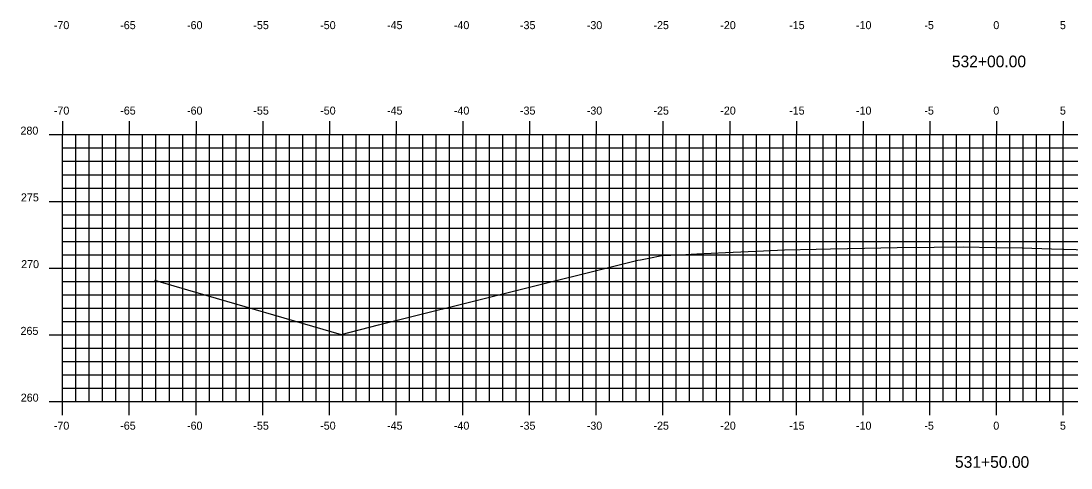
# Model space of a CAD drawing. Extents: x 1170543 to 1177585, y 609599 to 610623.
# Drawn here: x 1176762.5 to 1176841.2, y 610272.8 to 610306.3 of the extents above; entities that cross this region are included whole.
import ezdxf

# ---------------------------------------------------------------- set-up
doc = ezdxf.new("R2010")
doc.units = 0
for name, color, linetype in [('H_V ANNOTATION', 7, 'Continuous'), ('MAJOR', 7, 'Continuous'), ('MINOR', 7, 'Continuous'), ('S_Roadway_Centerline', 7, 'Continuous')]:
    doc.layers.add(name, color=color, linetype=linetype)

msp = doc.modelspace()

# ---------------------------------------------------------------- linework, layer by layer
at = {"layer": 'MAJOR'}
for p, q in [((1176765.654, 610298.803), (1176765.654, 610297.801)), ((1176770.654, 610298.803), (1176770.654, 610297.801)), ((1176775.654, 610298.803), (1176775.654, 610297.801)), ((1176780.654, 610298.803), (1176780.654, 610297.801)), ((1176785.654, 610298.803), (1176785.654, 610297.801)), ((1176790.654, 610298.803), (1176790.654, 610297.801)), ((1176795.654, 610298.803), (1176795.654, 610297.801)), ((1176800.654, 610298.803), (1176800.654, 610297.801)), ((1176805.654, 610298.803), (1176805.654, 610297.801)), ((1176810.654, 610298.803), (1176810.654, 610297.801)), ((1176815.654, 610298.803), (1176815.654, 610297.801)), ((1176820.654, 610298.803), (1176820.654, 610297.801)), ((1176825.654, 610298.803), (1176825.654, 610297.801)), ((1176830.654, 610298.803), (1176830.654, 610297.801)), ((1176835.654, 610298.803), (1176835.654, 610297.801)), ((1176840.654, 610298.803), (1176840.654, 610297.801)), ((1176764.652, 610297.801), (1176765.654, 610297.801)), ((1176765.654, 610297.801), (1176905.654, 610297.801)), ((1176765.654, 610277.801), (1176765.654, 610297.801)), ((1176765.654, 610277.801), (1176765.654, 610297.801)), ((1176765.654, 610297.801), (1176905.654, 610297.801)), ((1176770.654, 610277.801), (1176770.654, 610297.801)), ((1176775.654, 610277.801), (1176775.654, 610297.801)), ((1176780.654, 610277.801), (1176780.654, 610297.801)), ((1176785.654, 610277.801), (1176785.654, 610297.801)), ((1176790.654, 610277.801), (1176790.654, 610297.801)), ((1176795.654, 610277.801), (1176795.654, 610297.801)), ((1176800.654, 610277.801), (1176800.654, 610297.801)), ((1176805.654, 610277.801), (1176805.654, 610297.801)), ((1176810.654, 610277.801), (1176810.654, 610297.801)), ((1176815.654, 610277.801), (1176815.654, 610297.801)), ((1176820.654, 610277.801), (1176820.654, 610297.801)), ((1176825.654, 610277.801), (1176825.654, 610297.801)), ((1176830.654, 610277.801), (1176830.654, 610297.801)), ((1176835.654, 610277.801), (1176835.654, 610297.801)), ((1176840.654, 610277.801), (1176840.654, 610297.801)), ((1176764.652, 610292.801), (1176765.654, 610292.801)), ((1176765.654, 610292.801), (1176905.654, 610292.801)), ((1176764.652, 610287.801), (1176765.654, 610287.801)), ((1176765.654, 610287.801), (1176905.654, 610287.801)), ((1176764.652, 610282.801), (1176765.654, 610282.801)), ((1176765.654, 610282.801), (1176905.654, 610282.801)), ((1176764.652, 610277.801), (1176765.654, 610277.801)), ((1176765.654, 610277.801), (1176905.654, 610277.801)), ((1176765.654, 610277.801), (1176905.654, 610277.801)), ((1176765.654, 610276.799), (1176765.654, 610277.801)), ((1176770.654, 610276.799), (1176770.654, 610277.801)), ((1176775.654, 610276.799), (1176775.654, 610277.801)), ((1176780.654, 610276.799), (1176780.654, 610277.801)), ((1176785.654, 610276.799), (1176785.654, 610277.801)), ((1176790.654, 610276.799), (1176790.654, 610277.801)), ((1176795.654, 610276.799), (1176795.654, 610277.801)), ((1176800.654, 610276.799), (1176800.654, 610277.801)), ((1176805.654, 610276.799), (1176805.654, 610277.801)), ((1176810.654, 610276.799), (1176810.654, 610277.801)), ((1176815.654, 610276.799), (1176815.654, 610277.801)), ((1176820.654, 610276.799), (1176820.654, 610277.801)), ((1176825.654, 610276.799), (1176825.654, 610277.801)), ((1176830.654, 610276.799), (1176830.654, 610277.801)), ((1176835.654, 610276.799), (1176835.654, 610277.801)), ((1176840.654, 610276.799), (1176840.654, 610277.801))]:
    msp.add_line(p, q, dxfattribs=at)
at = {"layer": 'MINOR'}
for p, q in [((1176766.654, 610277.801), (1176766.654, 610297.801)), ((1176767.654, 610277.801), (1176767.654, 610297.801)), ((1176768.654, 610277.801), (1176768.654, 610297.801)), ((1176769.654, 610277.801), (1176769.654, 610297.801)), ((1176771.654, 610277.801), (1176771.654, 610297.801)), ((1176772.654, 610277.801), (1176772.654, 610297.801)), ((1176773.654, 610277.801), (1176773.654, 610297.801)), ((1176774.654, 610277.801), (1176774.654, 610297.801)), ((1176776.654, 610277.801), (1176776.654, 610297.801)), ((1176777.654, 610277.801), (1176777.654, 610297.801)), ((1176778.654, 610277.801), (1176778.654, 610297.801)), ((1176779.654, 610277.801), (1176779.654, 610297.801)), ((1176781.654, 610277.801), (1176781.654, 610297.801)), ((1176782.654, 610277.801), (1176782.654, 610297.801)), ((1176783.654, 610277.801), (1176783.654, 610297.801)), ((1176784.654, 610277.801), (1176784.654, 610297.801)), ((1176786.654, 610277.801), (1176786.654, 610297.801)), ((1176787.654, 610277.801), (1176787.654, 610297.801)), ((1176788.654, 610277.801), (1176788.654, 610297.801)), ((1176789.654, 610277.801), (1176789.654, 610297.801)), ((1176791.654, 610277.801), (1176791.654, 610297.801)), ((1176792.654, 610277.801), (1176792.654, 610297.801)), ((1176793.654, 610277.801), (1176793.654, 610297.801)), ((1176794.654, 610277.801), (1176794.654, 610297.801)), ((1176796.654, 610277.801), (1176796.654, 610297.801)), ((1176797.654, 610277.801), (1176797.654, 610297.801)), ((1176798.654, 610277.801), (1176798.654, 610297.801)), ((1176799.654, 610277.801), (1176799.654, 610297.801)), ((1176801.654, 610277.801), (1176801.654, 610297.801)), ((1176802.654, 610277.801), (1176802.654, 610297.801)), ((1176803.654, 610277.801), (1176803.654, 610297.801)), ((1176804.654, 610277.801), (1176804.654, 610297.801)), ((1176806.654, 610277.801), (1176806.654, 610297.801)), ((1176807.654, 610277.801), (1176807.654, 610297.801)), ((1176808.654, 610277.801), (1176808.654, 610297.801)), ((1176809.654, 610277.801), (1176809.654, 610297.801)), ((1176811.654, 610277.801), (1176811.654, 610297.801)), ((1176812.654, 610277.801), (1176812.654, 610297.801)), ((1176813.654, 610277.801), (1176813.654, 610297.801)), ((1176814.654, 610277.801), (1176814.654, 610297.801)), ((1176816.654, 610277.801), (1176816.654, 610297.801)), ((1176817.654, 610277.801), (1176817.654, 610297.801)), ((1176818.654, 610277.801), (1176818.654, 610297.801)), ((1176819.654, 610277.801), (1176819.654, 610297.801)), ((1176821.654, 610277.801), (1176821.654, 610297.801)), ((1176822.654, 610277.801), (1176822.654, 610297.801)), ((1176823.654, 610277.801), (1176823.654, 610297.801)), ((1176824.654, 610277.801), (1176824.654, 610297.801)), ((1176826.654, 610277.801), (1176826.654, 610297.801)), ((1176827.654, 610277.801), (1176827.654, 610297.801)), ((1176828.654, 610277.801), (1176828.654, 610297.801)), ((1176829.654, 610277.801), (1176829.654, 610297.801)), ((1176831.654, 610277.801), (1176831.654, 610297.801)), ((1176832.654, 610277.801), (1176832.654, 610297.801)), ((1176833.654, 610277.801), (1176833.654, 610297.801)), ((1176834.654, 610277.801), (1176834.654, 610297.801)), ((1176836.654, 610277.801), (1176836.654, 610297.801)), ((1176837.654, 610277.801), (1176837.654, 610297.801)), ((1176838.654, 610277.801), (1176838.654, 610297.801)), ((1176839.654, 610277.801), (1176839.654, 610297.801)), ((1176765.654, 610296.801), (1176905.654, 610296.801)), ((1176765.654, 610296.801), (1176766.656, 610296.801)), ((1176765.654, 610295.801), (1176905.654, 610295.801)), ((1176765.654, 610295.801), (1176766.656, 610295.801)), ((1176765.654, 610294.801), (1176905.654, 610294.801)), ((1176765.654, 610294.801), (1176766.656, 610294.801)), ((1176765.654, 610293.801), (1176905.654, 610293.801)), ((1176765.654, 610293.801), (1176766.656, 610293.801)), ((1176765.654, 610291.801), (1176905.654, 610291.801)), ((1176765.654, 610291.801), (1176766.656, 610291.801)), ((1176765.654, 610290.801), (1176905.654, 610290.801)), ((1176765.654, 610290.801), (1176766.656, 610290.801)), ((1176765.654, 610289.801), (1176905.654, 610289.801)), ((1176765.654, 610289.801), (1176766.656, 610289.801)), ((1176765.654, 610288.801), (1176905.654, 610288.801)), ((1176765.654, 610288.801), (1176766.656, 610288.801)), ((1176765.654, 610286.801), (1176905.654, 610286.801)), ((1176765.654, 610286.801), (1176766.656, 610286.801)), ((1176765.654, 610285.801), (1176905.654, 610285.801)), ((1176765.654, 610285.801), (1176766.656, 610285.801)), ((1176765.654, 610284.801), (1176905.654, 610284.801)), ((1176765.654, 610284.801), (1176766.656, 610284.801)), ((1176765.654, 610283.801), (1176905.654, 610283.801)), ((1176765.654, 610283.801), (1176766.656, 610283.801)), ((1176765.654, 610281.801), (1176905.654, 610281.801)), ((1176765.654, 610281.801), (1176766.656, 610281.801)), ((1176765.654, 610280.801), (1176905.654, 610280.801)), ((1176765.654, 610280.801), (1176766.656, 610280.801)), ((1176765.654, 610279.801), (1176905.654, 610279.801)), ((1176765.654, 610279.801), (1176766.656, 610279.801)), ((1176765.654, 610278.801), (1176905.654, 610278.801)), ((1176765.654, 610278.801), (1176766.656, 610278.801))]:
    msp.add_line(p, q, dxfattribs=at)
at = {"layer": 'S_Roadway_Centerline'}
msp.add_lwpolyline([(1176772.537, 610286.89), (1176775.016, 610286.165), (1176786.536, 610282.839), (1176789.322, 610283.565), (1176808.469, 610288.329), (1176808.776, 610288.394), (1176808.961, 610288.429), (1176809.605, 610288.553), (1176810.557, 610288.744), (1176811.943, 610288.809), (1176813.195, 610288.866), (1176815.345, 610288.962), (1176818.199, 610289.091), (1176819.771, 610289.163), (1176822.136, 610289.233), (1176823.203, 610289.238), (1176825.765, 610289.291), (1176828.206, 610289.342), (1176830.974, 610289.374), (1176833.21, 610289.4), (1176835.522, 610289.348), (1176837.564, 610289.309), (1176839.769, 610289.258), (1176848.1, 610289.014)], dxfattribs=at)

# ---------------------------------------------------------------- texts
at = {"layer": 'H_V ANNOTATION'}
for s, height, p in [('-70', 0.6, (1176764.996, 610305.701)), ('-65', 0.6, (1176769.972, 610305.701)), ('-60', 0.6, (1176774.98, 610305.701)), ('-55', 0.6, (1176779.951, 610305.701)), ('-50', 0.6, (1176784.959, 610305.701)), ('-45', 0.6, (1176789.972, 610305.701)), ('-40', 0.6, (1176794.98, 610305.701)), ('-35', 0.6, (1176799.935, 610305.701)), ('-30', 0.6, (1176804.943, 610305.701)), ('-25', 0.6, (1176809.94, 610305.701)), ('-20', 0.6, (1176814.948, 610305.701)), ('-15', 0.6, (1176820.111, 610305.701)), ('-10', 0.6, (1176825.119, 610305.701)), ('-5', 0.6, (1176830.245, 610305.701)), ('0', 0.6, (1176835.414, 610305.701)), ('5', 0.6, (1176840.406, 610305.701)), ('532+00.00', 0.875, (1176832.307, 610302.844)), ('-70', 0.6, (1176764.996, 610299.301)), ('-65', 0.6, (1176769.972, 610299.301)), ('-60', 0.6, (1176774.98, 610299.301)), ('-55', 0.6, (1176779.951, 610299.301)), ('-50', 0.6, (1176784.959, 610299.301)), ('-45', 0.6, (1176789.972, 610299.301)), ('-40', 0.6, (1176794.98, 610299.301)), ('-35', 0.6, (1176799.935, 610299.301)), ('-30', 0.6, (1176804.943, 610299.301)), ('-25', 0.6, (1176809.94, 610299.301)), ('-20', 0.6, (1176814.948, 610299.301)), ('-15', 0.6, (1176820.111, 610299.301)), ('-10', 0.6, (1176825.119, 610299.301)), ('-5', 0.6, (1176830.245, 610299.301)), ('0', 0.6, (1176835.414, 610299.301)), ('5', 0.6, (1176840.406, 610299.301)), ('280', 0.6, (1176762.495, 610297.801)), ('275', 0.6, (1176762.532, 610292.801)), ('270', 0.6, (1176762.548, 610287.801)), ('265', 0.6, (1176762.501, 610282.801)), ('260', 0.6, (1176762.517, 610277.801)), ('-70', 0.6, (1176764.996, 610275.701)), ('-65', 0.6, (1176769.972, 610275.701)), ('-60', 0.6, (1176774.98, 610275.701)), ('-55', 0.6, (1176779.951, 610275.701)), ('-50', 0.6, (1176784.959, 610275.701)), ('-45', 0.6, (1176789.972, 610275.701)), ('-40', 0.6, (1176794.98, 610275.701)), ('-35', 0.6, (1176799.935, 610275.701)), ('-30', 0.6, (1176804.943, 610275.701)), ('-25', 0.6, (1176809.94, 610275.701)), ('-20', 0.6, (1176814.948, 610275.701)), ('-15', 0.6, (1176820.111, 610275.701)), ('-10', 0.6, (1176825.119, 610275.701)), ('-5', 0.6, (1176830.245, 610275.701)), ('0', 0.6, (1176835.414, 610275.701)), ('5', 0.6, (1176840.406, 610275.701)), ('531+50.00', 0.875, (1176832.541, 610272.844))]:
    msp.add_text(s, height=height, dxfattribs=at).set_placement(p)

doc.saveas('drawing.dxf')
